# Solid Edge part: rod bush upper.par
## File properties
Author: Robert a Rhodes jr
Template: Normal.par
Last saved by: CADCIM
Revision: 11
Application: Solid Edge
Accuracy: 0.99
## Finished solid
Body 1: solid body, 4 faces, 4 edges, 0 vertices.
  Faces by surface: cylinder 2, plane 2
  Edges by curve: circle 4
Bounding box of the edges (mm): 24.000 x 24.000 x 42.000, from (-12, -12, -42) to (12, 12, 0).
Cylindrical faces by radius (mm): R11 x1, R12 x1
Planar faces by outward normal: +z 1, -z 1
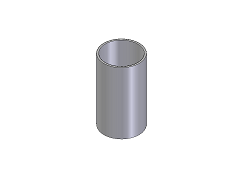
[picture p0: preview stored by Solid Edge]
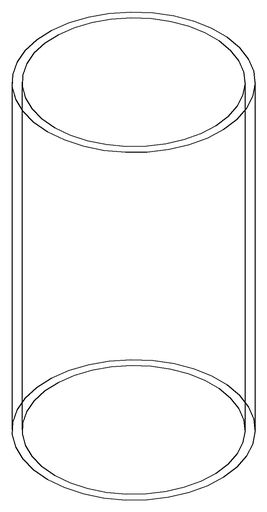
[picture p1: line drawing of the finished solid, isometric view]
